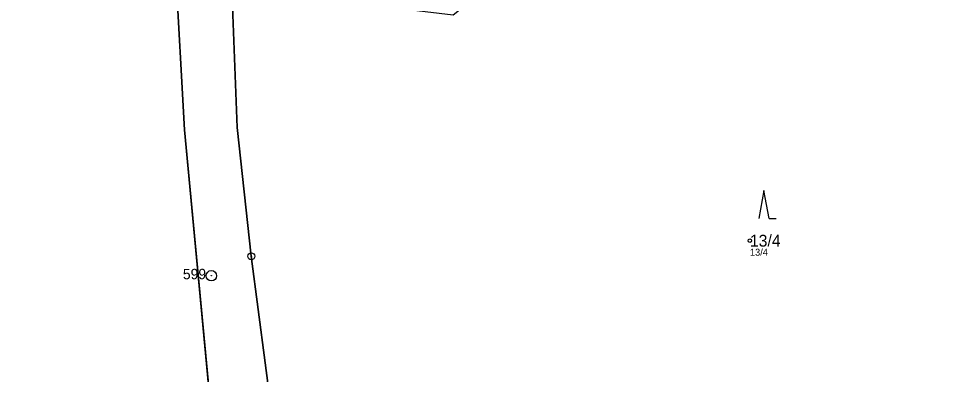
# Model space of a CAD drawing. Extents: x -732749 to -730903, y -1025757 to -1023435.
# Drawn here: x -732304 to -732171.3, y -1025590.5 to -1025539.2 of the extents above; entities that cross this region are included whole.
import ezdxf

# ---------------------------------------------------------------- set-up
doc = ezdxf.new("R2010")
doc.units = 0
for name, color, linetype in [('Definiční body', 7, 'Continuous'), ('Hranice parcel', 7, 'Continuous'), ('Parcelní čísla', 7, 'Continuous'), ('Polygon parcely', 7, 'Continuous'), ('Značky bodu BP', 7, 'Continuous'), ('Značky kultur', 7, 'Continuous')]:
    doc.layers.add(name, color=color, linetype=linetype)

msp = doc.modelspace()

# ---------------------------------------------------------------- linework, layer by layer
at = {"layer": 'Definiční body'}
msp.add_circle((-732198.64, -1025571.21), 0.25, dxfattribs=at)
at = {"layer": 'Hranice parcel'}
for p, q in [((-732280.05, -1025555.26), (-732281.35, -1025531.97)), ((-732273.25, -1025534.93), (-732272.48, -1025554.91)), ((-732276.07, -1025597.41), (-732280.05, -1025555.26))]:
    msp.add_line(p, q, dxfattribs=at)
msp.add_lwpolyline([(-732272.48, -1025554.91), (-732270.44, -1025573.45), (-732267.4, -1025596.45), (-732266.56, -1025618.69)], dxfattribs=at)
at = {"layer": 'Polygon parcely'}
for points in [[(-732304.25, -1025400.3), (-732303.48, -1025404.78), (-732302.69, -1025406.69), (-732301.04, -1025410.65), (-732299.04, -1025420.48), (-732297.84, -1025426.05), (-732293.35, -1025448.12), (-732292.02, -1025456.42), (-732291.37, -1025460.78), (-732290.49, -1025469.28), (-732286.02, -1025510.73), (-732281.72, -1025525.37), (-732281.35, -1025531.97), (-732280.05, -1025555.26), (-732276.07, -1025597.41)], [(-732267.4, -1025596.45), (-732270.44, -1025573.45), (-732272.48, -1025554.91), (-732273.25, -1025534.93), (-732273.69, -1025523.61), (-732275.16, -1025511.98), (-732276.15, -1025504.02), (-732276.7, -1025499.73), (-732279.34, -1025478.79), (-732280.54, -1025469.25), (-732280.93, -1025466.15), (-732287.81, -1025433.42)]]:
    msp.add_lwpolyline(points, dxfattribs=at)
for points in [[(-732238.97, -1025655.62), (-732223.93, -1025660.81), (-732213.48, -1025653.81), (-732205.87, -1025647.71), (-732193.5, -1025634.71), (-732176.01, -1025613.14), (-732153.23, -1025583.75), (-732141.86, -1025569.31), (-732117.18, -1025522.81), (-732143.59, -1025491.56), (-732161.47, -1025469.94), (-732165.68, -1025473.97), (-732189.29, -1025497.4), (-732241.34, -1025538.74), (-732273.25, -1025534.93), (-732272.48, -1025554.91), (-732270.44, -1025573.45), (-732267.4, -1025596.45), (-732266.56, -1025618.69), (-732268.12, -1025634.65), (-732271.39, -1025643.7)], [(-732280.05, -1025555.26), (-732281.35, -1025531.97), (-732308.73, -1025528.38), (-732323.76, -1025532.34), (-732342.86, -1025551.82), (-732382.24, -1025585.02), (-732398.83, -1025586.43), (-732397.53, -1025587.54), (-732359.24, -1025619.52), (-732324.25, -1025648.2), (-732295.21, -1025603.47), (-732274.79, -1025614.32), (-732276.07, -1025597.41)]]:
    msp.add_lwpolyline(points, close=True, dxfattribs=at)
at = {"layer": 'Značky bodu BP'}
for centre, radius in [((-732270.44, -1025573.45), 0.5), ((-732270.44, -1025573.45), 0.0303), ((-732276.18, -1025576.26), 0.75), ((-732276.18, -1025576.26), 0.03)]:
    msp.add_circle(centre, radius, dxfattribs=at)
at = {"layer": 'Značky kultur'}
for p, q in [((-732196.62, -1025564), (-732197.37, -1025568)), ((-732195.87, -1025568), (-732196.62, -1025564)), ((-732195.87, -1025568), (-732194.87, -1025568))]:
    msp.add_line(p, q, dxfattribs=at)

# ---------------------------------------------------------------- texts
at = {"layer": 'Definiční body'}
msp.add_text('13/4', height=1, dxfattribs=at).set_placement((-732198.64, -1025573.37))
at = {"layer": 'Parcelní čísla'}
msp.add_text('13/4', height=1.7, dxfattribs=at).set_placement((-732198.64, -1025572.06))
at = {"layer": 'Značky bodu BP'}
msp.add_text('599', height=1.5, dxfattribs=at).set_placement((-732280.28, -1025576.76))

doc.saveas('drawing.dxf')
